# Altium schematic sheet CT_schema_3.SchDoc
size 395 x 205 mm
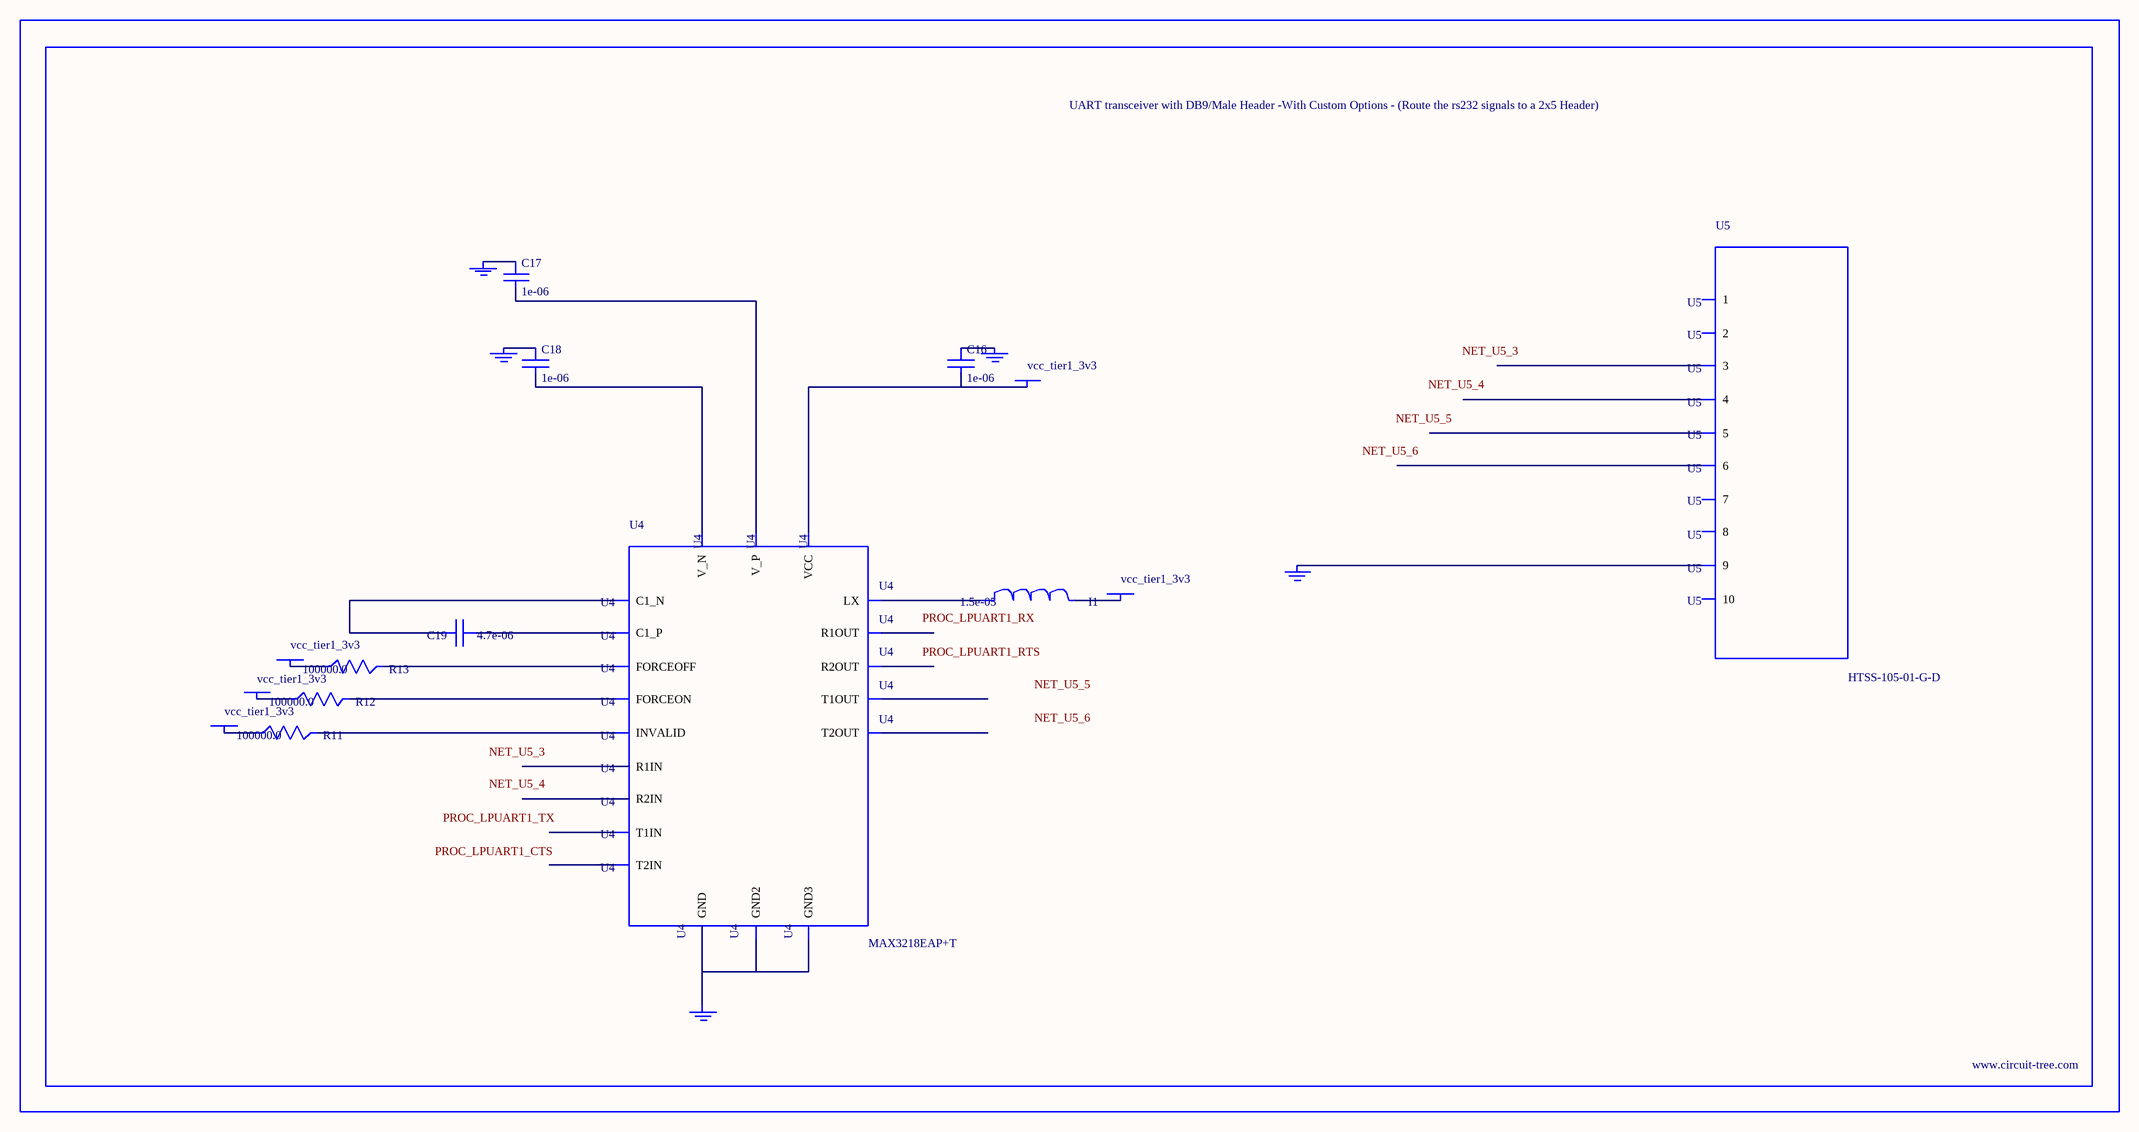
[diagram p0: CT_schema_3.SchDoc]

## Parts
BORDER2  (no value)
C16  1e-06  [C0603]
C17  1e-06  [C0603]
C18  1e-06  [C0603]
C19  4.7e-06  [C0805]
GND_INSTANCE_2_0  (no value)
GND_INSTANCE_2_1  (no value)
GND_INSTANCE_2_2  (no value)
GND_INSTANCE_2_3  (no value)
GND_INSTANCE_2_4  (no value)
I1  1.5e-05  [L1210]
POWER_INSTANCE_2_0  vcc_tier1_3v3
POWER_INSTANCE_2_1  vcc_tier1_3v3
POWER_INSTANCE_2_2  vcc_tier1_3v3
POWER_INSTANCE_2_3  vcc_tier1_3v3
POWER_INSTANCE_2_4  vcc_tier1_3v3
R11  100000.0  [R0603]
R12  100000.0  [R0603]
R13  100000.0  [R0603]
U4  MAX3218EAP+T  [SSOP-20]
U5  HTSS-105-01-G-D  [HTSS-105-01-G-D]

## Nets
NetC16_1: C16.1 GND_INSTANCE_2_0.0(GND)
NetC16_2: C16.2 POWER_INSTANCE_2_4.0(PWR) U4.6(VCC)
NetC17_1: C17.1 GND_INSTANCE_2_2.0(GND)
NetC17_2: C17.2 U4.19(V_P)
NetC18_1: C18.1 GND_INSTANCE_2_1.0(GND)
NetC18_2: C18.2 U4.15(V_N)
NetC19_1: C19.1 U4.18(C1_P)
NetC19_2: C19.2 U4.16(C1_N)
NetGND_INSTANCE_2_3_0: GND_INSTANCE_2_3.0(GND) U4.5(GND) U4.17(GND2) U4.20(GND3)
NetGND_INSTANCE_2_4_0: GND_INSTANCE_2_4.0(GND) U5.9
NetI1_1: I1.1 U4.1(LX)
NetI1_2: I1.2 POWER_INSTANCE_2_0.0(PWR)
NetPOWER_INSTANCE_2_1_0: POWER_INSTANCE_2_1.0(PWR) R11.1
NetPOWER_INSTANCE_2_2_0: POWER_INSTANCE_2_2.0(PWR) R12.1
NetPOWER_INSTANCE_2_3_0: POWER_INSTANCE_2_3.0(PWR) R13.1
NetR11_2: R11.2 U4.2(INVALID)
NetR12_2: R12.2 U4.3(FORCEON)
NetR13_2: R13.2 U4.4(FORCEOFF)

Not connected (* = marked no-connect by the designer): U4 7(T1IN) 8(T2IN) 9(R1OUT) 10(R2OUT) 11(R2IN) 12(R1IN) 13(T2OUT) 14(T1OUT); U5 1 2 3 4 5 6 7 8 10

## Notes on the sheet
- Labels drawn without touching a wire or pin: NET_U5_3, NET_U5_4, NET_U5_5, NET_U5_6, PROC_LPUART1_CTS, PROC_LPUART1_RTS, PROC_LPUART1_RX, PROC_LPUART1_TX

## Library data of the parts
BORDER2 = BORDER_PAGE2
C16-C18 = C0603C105K3RACTU
C19 = C0805C475K4RACTU
GND_INSTANCE_2_0-GND_INSTANCE_2_4 = GND
I1 = L1210R150MDWIT
POWER_INSTANCE_2_0-POWER_INSTANCE_2_4 = PWR
R11-R13 = RC0603JR-07100KL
